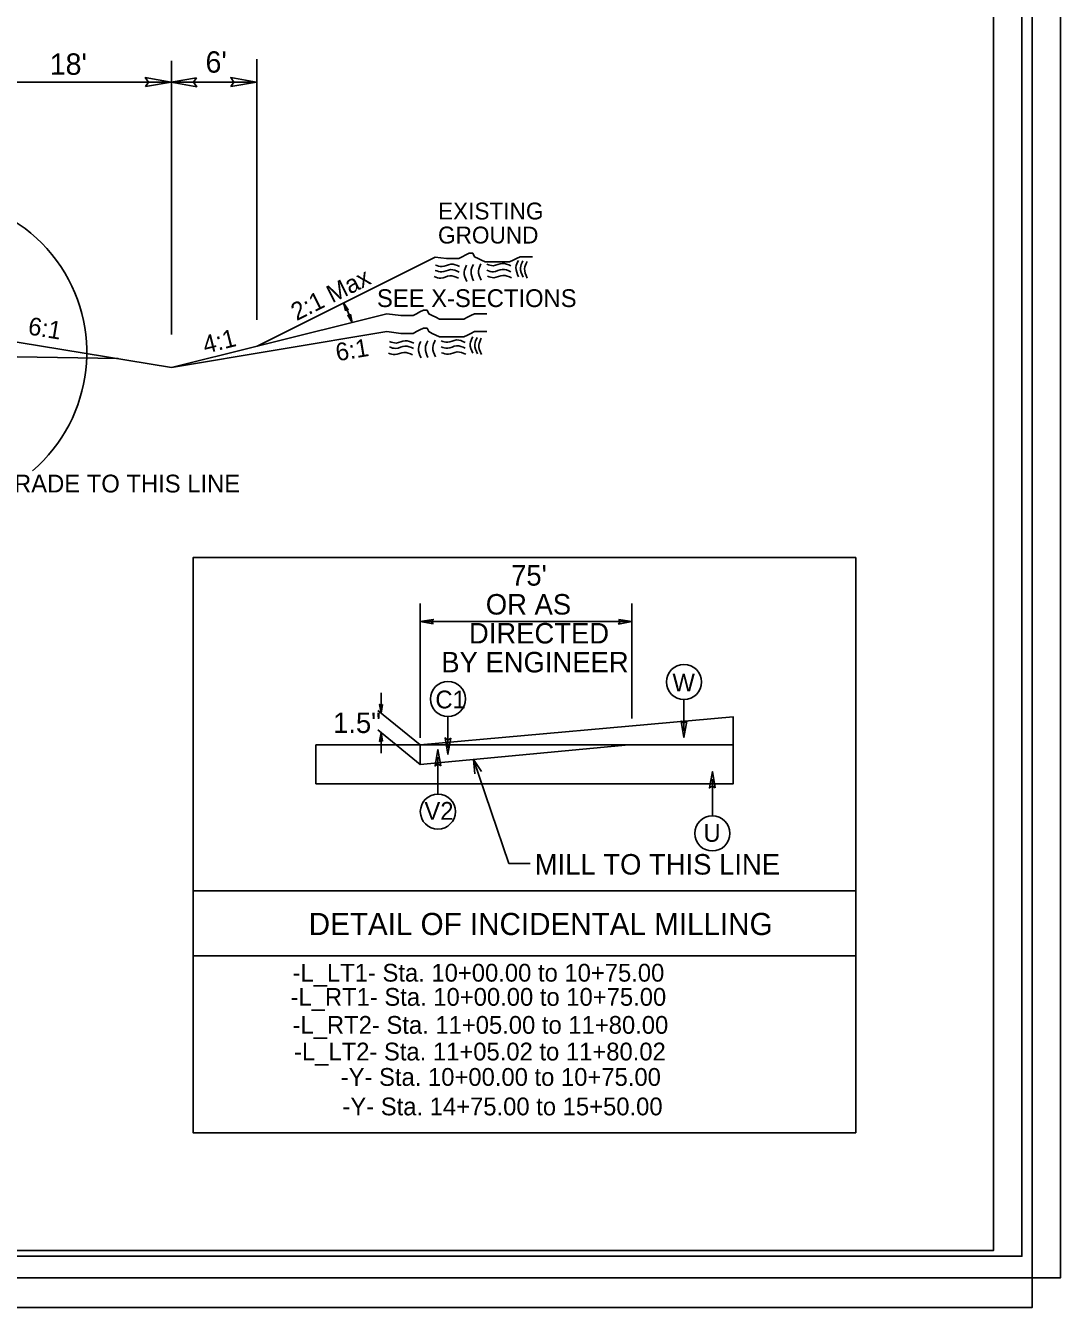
# Model space of a CAD drawing. Extents: x 2294455 to 2294842, y 719496 to 719941.
# Drawn here: x 2294702.9 to 2294793.8, y 719496.2 to 719608.7 of the extents above; entities that cross this region are included whole.
import ezdxf

# ---------------------------------------------------------------- set-up
doc = ezdxf.new("R2010")
doc.units = 0
for name, color, linetype in [('Old_Level_1', 7, 'Continuous'), ('Old_Level_11', 7, 'Continuous'), ('Old_Level_2', 7, 'Continuous'), ('Old_Level_3', 7, 'Continuous'), ('Prop Dimension Text', 7, 'Continuous'), ('Prop Shade Light', 7, 'Continuous'), ('Prop XS Finish Grade', 7, 'Continuous'), ('Prop XS Side Slope Text', 7, 'Continuous'), ('Sheet Cutting Line CELL', 7, 'Continuous'), ('Sheet Plot Border Inside CELL', 7, 'Continuous'), ('Sheet Plot Border Outside CELL', 7, 'Continuous'), ('Sheet Typical CELL', 7, 'Continuous'), ('Typical Hinge Slope Arterial CELL', 7, 'Continuous'), ('Typical Hinge Slope Interstate CELL', 7, 'Continuous'), ('Typical ID Circle CELL', 7, 'Continuous'), ('Typical Pavement Slope CELL', 7, 'Continuous'), ('Typical Terminator CELL', 7, 'Continuous'), ('Typical Text ID Circle CELL', 7, 'Continuous')]:
    doc.layers.add(name, color=color, linetype=linetype)

msp = doc.modelspace()

# ---------------------------------------------------------------- linework, layer by layer
at = {"layer": 'Old_Level_1'}
msp.add_line((2294694.26, 719579.76), (2294711.07, 719579.47), dxfattribs=at)
at = {"layer": 'Old_Level_11'}
for p, q in [((2294715.73, 719581.6), (2294715.73, 719605.61)), ((2294723.23, 719582.88), (2294723.23, 719605.78)), ((2294715.7, 719603.75), (2294696.95, 719603.75)), ((2294723.2, 719603.75), (2294715.7, 719603.75))]:
    msp.add_line(p, q, dxfattribs=at)
for points in [[(2294713.45, 719603.36), (2294715.7, 719603.75), (2294713.44, 719604.15), (2294713.73, 719603.75)], [(2294717.95, 719604.14), (2294715.7, 719603.75), (2294717.96, 719603.35), (2294717.68, 719603.75)], [(2294720.95, 719603.36), (2294723.2, 719603.75), (2294720.94, 719604.15), (2294721.22, 719603.75)]]:
    msp.add_lwpolyline(points, close=True, dxfattribs=at)
msp.add_arc((2294694.63, 719579.99), 13.67, 310.6874, 293.4994, dxfattribs=at)
at = {"layer": 'Old_Level_2'}
for points in [[(2294741.01, 719587.07), (2294740.25, 719587.29), (2294739.46, 719587.09), (2294738.89, 719587.22)], [(2294741.01, 719587.07), (2294740.25, 719587.29), (2294739.46, 719587.09), (2294738.89, 719587.22)], [(2294741.03, 719587.55), (2294740.27, 719587.76), (2294739.48, 719587.56), (2294738.91, 719587.69)], [(2294741.03, 719587.55), (2294740.27, 719587.76), (2294739.48, 719587.56), (2294738.91, 719587.69)], [(2294741.65, 719587.69), (2294741.44, 719587.07), (2294741.66, 719586.25)], [(2294741.65, 719587.69), (2294741.44, 719587.07), (2294741.66, 719586.25)], [(2294742.25, 719587.74), (2294742.04, 719587.12), (2294742.27, 719586.3)], [(2294742.25, 719587.74), (2294742.04, 719587.12), (2294742.27, 719586.3)], [(2294742.91, 719587.8), (2294742.7, 719587.18), (2294742.92, 719586.35)], [(2294742.91, 719587.8), (2294742.7, 719587.18), (2294742.92, 719586.35)], [(2294745.54, 719587.62), (2294744.79, 719587.83), (2294743.99, 719587.63), (2294743.42, 719587.76)], [(2294745.54, 719587.62), (2294744.79, 719587.83), (2294743.99, 719587.63), (2294743.42, 719587.76)], [(2294745.54, 719587.1), (2294744.79, 719587.31), (2294744, 719587.1), (2294743.43, 719587.23)], [(2294745.54, 719587.1), (2294744.79, 719587.31), (2294744, 719587.1), (2294743.43, 719587.23)], [(2294746.2, 719588.1), (2294745.99, 719587.48), (2294746.22, 719586.66)], [(2294746.2, 719588.1), (2294745.99, 719587.48), (2294746.22, 719586.66)], [(2294746.59, 719588.06), (2294746.38, 719587.44), (2294746.61, 719586.62)], [(2294746.59, 719588.06), (2294746.38, 719587.44), (2294746.61, 719586.62)], [(2294746.96, 719587.99), (2294746.75, 719587.37), (2294746.97, 719586.55)], [(2294746.96, 719587.99), (2294746.75, 719587.37), (2294746.97, 719586.55)], [(2294740.93, 719586.53), (2294740.18, 719586.74), (2294739.38, 719586.54), (2294738.81, 719586.67)], [(2294740.93, 719586.53), (2294740.18, 719586.74), (2294739.38, 719586.54), (2294738.81, 719586.67)], [(2294745.6, 719586.57), (2294744.85, 719586.78), (2294744.05, 719586.58), (2294743.48, 719586.71)], [(2294745.6, 719586.57), (2294744.85, 719586.78), (2294744.05, 719586.58), (2294743.48, 719586.71)], [(2294742.19, 719581.38), (2294741.97, 719580.76), (2294742.2, 719579.94)], [(2294742.19, 719581.38), (2294741.97, 719580.76), (2294742.2, 719579.94)], [(2294736.99, 719580.36), (2294736.24, 719580.57), (2294735.45, 719580.37), (2294734.87, 719580.5)], [(2294736.99, 719580.36), (2294736.24, 719580.57), (2294735.45, 719580.37), (2294734.87, 719580.5)], [(2294737.01, 719580.83), (2294736.26, 719581.04), (2294735.47, 719580.84), (2294734.89, 719580.97)], [(2294737.01, 719580.83), (2294736.26, 719581.04), (2294735.47, 719580.84), (2294734.89, 719580.97)], [(2294737.63, 719580.97), (2294737.42, 719580.35), (2294737.65, 719579.53)], [(2294737.63, 719580.97), (2294737.42, 719580.35), (2294737.65, 719579.53)], [(2294738.24, 719581.03), (2294738.03, 719580.4), (2294738.25, 719579.58)], [(2294738.24, 719581.03), (2294738.03, 719580.4), (2294738.25, 719579.58)], [(2294738.89, 719581.08), (2294738.69, 719580.46), (2294738.91, 719579.63)], [(2294738.89, 719581.08), (2294738.69, 719580.46), (2294738.91, 719579.63)], [(2294741.52, 719580.9), (2294740.77, 719581.11), (2294739.98, 719580.91), (2294739.41, 719581.04)], [(2294741.52, 719580.9), (2294740.77, 719581.11), (2294739.98, 719580.91), (2294739.41, 719581.04)], [(2294741.53, 719580.38), (2294740.77, 719580.59), (2294739.98, 719580.39), (2294739.41, 719580.51)], [(2294741.53, 719580.38), (2294740.77, 719580.59), (2294739.98, 719580.39), (2294739.41, 719580.51)], [(2294742.58, 719581.34), (2294742.37, 719580.72), (2294742.6, 719579.9)], [(2294742.58, 719581.34), (2294742.37, 719580.72), (2294742.6, 719579.9)], [(2294742.94, 719581.27), (2294742.73, 719580.65), (2294742.96, 719579.83)], [(2294742.94, 719581.27), (2294742.73, 719580.65), (2294742.96, 719579.83)], [(2294736.91, 719579.81), (2294736.16, 719580.02), (2294735.37, 719579.82), (2294734.79, 719579.95)], [(2294736.91, 719579.81), (2294736.16, 719580.02), (2294735.37, 719579.82), (2294734.79, 719579.95)], [(2294741.59, 719579.85), (2294740.83, 719580.06), (2294740.04, 719579.86), (2294739.46, 719579.99)], [(2294741.59, 719579.85), (2294740.83, 719580.06), (2294740.04, 719579.86), (2294739.46, 719579.99)]]:
    msp.add_spline(points, degree=3, dxfattribs=at)
at = {"layer": 'Prop Shade Light'}
msp.add_lwpolyline([(2294737.57, 719545.55), (2294737.57, 719543.84), (2294755.89, 719545.55), (2294765.05, 719545.55), (2294765.05, 719548.03)], close=True, dxfattribs=at)
at = {"layer": 'Prop XS Finish Grade'}
msp.add_lwpolyline([(2294728.42, 719542.13), (2294765.05, 719542.13), (2294765.05, 719545.55), (2294728.42, 719545.55)], close=True, dxfattribs=at)
at = {"layer": 'Prop XS Side Slope Text'}
for p, q in [((2294737.57, 719546.19), (2294737.57, 719557.97)), ((2294756.16, 719547.86), (2294756.16, 719557.97)), ((2294737.57, 719556.38), (2294756.16, 719556.38)), ((2294734.15, 719550.14), (2294734.15, 719548.34)), ((2294737.57, 719545.55), (2294733.85, 719548.58)), ((2294737.57, 719543.84), (2294733.85, 719546.87)), ((2294734.15, 719544.84), (2294734.15, 719546.63))]:
    msp.add_line(p, q, dxfattribs=at)
at = {"layer": 'Sheet Cutting Line CELL'}
msp.add_line((2294454.52, 719496.17), (2294791.32, 719496.17), dxfattribs=at)
at = {"layer": 'Sheet Plot Border Inside CELL'}
msp.add_lwpolyline([(2294790.42, 719711.68), (2294457.12, 719711.68), (2294457.12, 719500.66), (2294790.42, 719500.66)], close=True, dxfattribs=at)
at = {"layer": 'Sheet Plot Border Outside CELL'}
for points in [[(2294793.79, 719718.76), (2294456.99, 719718.76), (2294456.99, 719498.76), (2294793.79, 719498.76)], [(2294791.32, 719716.17), (2294454.52, 719716.17), (2294454.52, 719496.17), (2294791.32, 719496.17)]]:
    msp.add_lwpolyline(points, close=True, dxfattribs=at)
at = {"layer": 'Sheet Typical CELL'}
msp.add_lwpolyline([(2294787.92, 719711.17), (2294487.92, 719711.17), (2294487.92, 719501.17), (2294787.92, 719501.17)], close=True, dxfattribs=at)
at = {"layer": 'Typical Hinge Slope Arterial CELL'}
for p, q in [((2294738.9, 719588.39), (2294723.25, 719580.57)), ((2294734.64, 719583.41), (2294723.25, 719580.57)), ((2294734.64, 719581.84), (2294715.75, 719578.69)), ((2294723.25, 719580.57), (2294715.75, 719578.69))]:
    msp.add_line(p, q, dxfattribs=at)
for points in [[(2294738.9, 719588.39), (2294739.88, 719588.27), (2294740.19, 719588.27), (2294740.65, 719588.27), (2294740.96, 719588.27), (2294741.27, 719588.42), (2294741.58, 719588.58), (2294741.89, 719588.73), (2294742.19, 719588.73), (2294742.35, 719588.42), (2294742.66, 719588.27), (2294742.96, 719588.11), (2294743.27, 719587.96), (2294743.58, 719587.96), (2294743.89, 719587.96), (2294744.2, 719587.96), (2294744.5, 719587.96), (2294744.81, 719587.96), (2294745.12, 719587.96), (2294745.43, 719587.96), (2294745.74, 719588.11), (2294746.04, 719588.27), (2294746.35, 719588.42), (2294746.82, 719588.42), (2294747.12, 719588.42), (2294747.43, 719588.42)], [(2294734.64, 719583.41), (2294735.87, 719583.26), (2294736.18, 719583.26), (2294736.64, 719583.26), (2294736.95, 719583.26), (2294737.26, 719583.41), (2294737.56, 719583.57), (2294737.87, 719583.72), (2294738.18, 719583.72), (2294738.33, 719583.41), (2294738.64, 719583.26), (2294738.95, 719583.11), (2294739.26, 719582.95), (2294739.57, 719582.95), (2294739.87, 719582.95), (2294740.18, 719582.95), (2294740.49, 719582.95), (2294740.8, 719582.95), (2294741.11, 719582.95), (2294741.41, 719582.95), (2294741.72, 719583.11), (2294742.03, 719583.26), (2294742.34, 719583.41), (2294742.8, 719583.41), (2294743.11, 719583.41), (2294743.42, 719583.41)], [(2294734.64, 719581.84), (2294735.87, 719581.69), (2294736.18, 719581.69), (2294736.64, 719581.69), (2294736.95, 719581.69), (2294737.26, 719581.84), (2294737.56, 719581.99), (2294737.87, 719582.15), (2294738.18, 719582.15), (2294738.33, 719581.84), (2294738.64, 719581.69), (2294738.95, 719581.53), (2294739.26, 719581.38), (2294739.57, 719581.38), (2294739.87, 719581.38), (2294740.18, 719581.38), (2294740.49, 719581.38), (2294740.8, 719581.38), (2294741.11, 719581.38), (2294741.41, 719581.38), (2294741.72, 719581.53), (2294742.03, 719581.69), (2294742.34, 719581.84), (2294742.8, 719581.84), (2294743.11, 719581.84), (2294743.42, 719581.84)]]:
    msp.add_lwpolyline(points, dxfattribs=at)
at = {"layer": 'Typical Hinge Slope Interstate CELL'}
msp.add_line((2294697.03, 719581.76), (2294715.75, 719578.69), dxfattribs=at)
msp.add_arc((2294723.25, 719579.94), 8.77, 18.0001, 30.219, dxfattribs=at)
at = {"layer": 'Typical ID Circle CELL'}
for p, q in [((2294760.74, 719549.53), (2294760.74, 719546.79)), ((2294740.01, 719548.05), (2294740.01, 719545.3)), ((2294739.13, 719541.25), (2294739.13, 719544.48)), ((2294742.27, 719544.28), (2294745.37, 719535.13)), ((2294742.96, 719543.22), (2294742.27, 719544.28)), ((2294742.38, 719543.02), (2294742.27, 719544.28)), ((2294763.23, 719539.32), (2294763.23, 719542.55)), ((2294745.37, 719535.13), (2294747.22, 719535.13))]:
    msp.add_line(p, q, dxfattribs=at)
for centre in [(2294760.74, 719551.08), (2294740.01, 719549.59), (2294739.13, 719539.7), (2294763.23, 719537.78)]:
    msp.add_circle(centre, 1.54, dxfattribs=at)
at = {"layer": 'Typical Pavement Slope CELL'}
for p, q in [((2294737.57, 719545.55), (2294765.05, 719548.03)), ((2294765.05, 719545.55), (2294765.05, 719548.03)), ((2294737.57, 719543.84), (2294755.89, 719545.55)), ((2294737.57, 719543.84), (2294737.57, 719545.55)), ((2294755.89, 719545.55), (2294765.05, 719545.55))]:
    msp.add_line(p, q, dxfattribs=at)
for points in [[(2294717.63, 719532.74), (2294775.83, 719532.74), (2294775.83, 719562), (2294717.63, 719562)], [(2294775.83, 719527.03), (2294717.63, 719527.03), (2294717.63, 719532.74), (2294775.83, 719532.74)], [(2294775.83, 719511.49), (2294717.65, 719511.49), (2294717.65, 719527.03), (2294775.83, 719527.03)]]:
    msp.add_lwpolyline(points, close=True, dxfattribs=at)
at = {"layer": 'Typical Terminator CELL'}
for points in [[(2294731.03, 719583.66), (2294730.83, 719584.36), (2294731.26, 719583.76), (2294731.1, 719583.79)], [(2294731.46, 719583.37), (2294731.59, 719582.65), (2294731.22, 719583.28), (2294731.37, 719583.24)], [(2294738.72, 719556.18), (2294737.57, 719556.38), (2294738.73, 719556.58), (2294738.58, 719556.38)], [(2294755.01, 719556.57), (2294756.16, 719556.38), (2294755, 719556.17), (2294755.15, 719556.38)], [(2294734.28, 719549.11), (2294734.15, 719548.34), (2294734.01, 719549.11), (2294734.15, 719549.01)], [(2294760.99, 719547.64), (2294760.74, 719546.21), (2294760.49, 719547.65), (2294760.74, 719547.47)], [(2294734.28, 719545.87), (2294734.15, 719546.63), (2294734.01, 719545.86), (2294734.15, 719545.96)], [(2294740.26, 719546.16), (2294740.01, 719544.73), (2294739.76, 719546.17), (2294740.01, 719545.98)], [(2294739.38, 719543.72), (2294739.13, 719545.15), (2294738.88, 719543.71), (2294739.13, 719543.89)], [(2294763.47, 719541.79), (2294763.23, 719543.22), (2294762.97, 719541.78), (2294763.23, 719541.97)]]:
    msp.add_lwpolyline(points, close=True, dxfattribs=at)

# ---------------------------------------------------------------- texts
at = {"layer": 'Old_Level_1'}
for s, height, p in [('EXISTING', 1.484, (2294739.14, 719591.69)), ('GROUND', 1.484, (2294739.14, 719589.58)), ('SEE X-SECTIONS', 1.5625, (2294733.78, 719584))]:
    msp.add_text(s, height=height, rotation=360, dxfattribs=at).set_placement(p)
at = {"layer": 'Old_Level_11'}
for s, p in [('GRADE TO THIS LINE', (2294700.29, 719567.72)), ('-L_LT1- Sta. 10+00.00 to 10+75.00', (2294726.37, 719524.77)), ('-L_RT1- Sta. 10+00.00 to 10+75.00', (2294726.19, 719522.65)), ('-L_RT2- Sta. 11+05.00 to 11+80.00', (2294726.37, 719520.19)), ('-L_LT2- Sta. 11+05.02 to 11+80.02', (2294726.5, 719517.85)), ('-Y- Sta. 10+00.00 to 10+75.00', (2294730.6, 719515.62)), ('-Y- Sta. 14+75.00 to 15+50.00', (2294730.75, 719513.03))]:
    msp.add_text(s, height=1.5625, rotation=360, dxfattribs=at).set_placement(p)
at = {"layer": 'Old_Level_3'}
for s, p in [("18'", (2294705.05, 719604.39)), ("6'", (2294718.73, 719604.58))]:
    msp.add_text(s, height=1.875, rotation=0.1671, dxfattribs=at).set_placement(p)
at = {"layer": 'Prop Dimension Text'}
msp.add_text('1.5"', height=1.8, dxfattribs=at).set_placement((2294729.93, 719546.6))
at = {"layer": 'Prop XS Side Slope Text'}
msp.add_text('MILL TO THIS LINE', height=1.8, rotation=360, dxfattribs=at).set_placement((2294747.64, 719534.17))
at = {"layer": 'Typical Hinge Slope Arterial CELL'}
msp.add_text('4:1', height=1.562, rotation=14.0362, dxfattribs=at).set_placement((2294718.71, 719579.89))
at = {"layer": 'Typical Hinge Slope Interstate CELL'}
for s, rotation, p in [('2:1 Max', 26.5651, (2294726.73, 719582.76)), ('6:1', 350.5377, (2294703.07, 719581.61)), ('6:1', 9.4623, (2294730.29, 719579.24))]:
    msp.add_text(s, height=1.562, rotation=rotation, dxfattribs=at).set_placement(p)
at = {"layer": 'Typical Pavement Slope CELL'}
for s, height, p in [("75'", 1.8, (2294745.56, 719559.54)), (' OR AS ', 1.8, (2294742.67, 719557)), ('DIRECTED ', 1.8, (2294741.86, 719554.46)), ('BY ENGINEER', 1.8, (2294739.43, 719551.92)), ('DETAIL OF INCIDENTAL MILLING', 1.9439, (2294727.79, 719528.86))]:
    msp.add_text(s, height=height, rotation=360, dxfattribs=at).set_placement(p)
at = {"layer": 'Typical Text ID Circle CELL'}
for s, height, p in [('W', 1.56, (2294759.73, 719550.25)), ('C1', 1.562, (2294738.91, 719548.76)), ('V2', 1.562, (2294737.95, 719538.98)), ('U', 1.56, (2294762.45, 719537.05))]:
    msp.add_text(s, height=height, dxfattribs=at).set_placement(p)

doc.saveas('drawing.dxf')
